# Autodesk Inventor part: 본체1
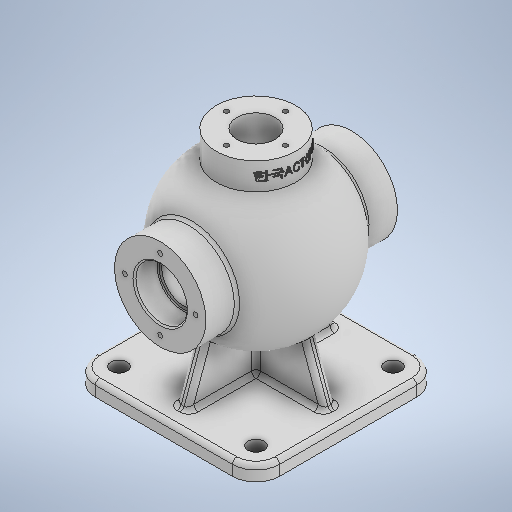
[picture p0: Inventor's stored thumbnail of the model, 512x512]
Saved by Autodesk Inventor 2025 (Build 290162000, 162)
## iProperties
Created: 2024-07
Part Number: 본체1
Material: 일반
Document SubType Name: Modeling
Designer: samsung
Density: 1 g/cm^3
Appearance: 기본값
Author: samsung
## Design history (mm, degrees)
sketch "스케치1"
  geometry: L1 (-46.5, -62.5)-(46.5, -62.5); L2 (62.5, -46.5)-(62.5, 46.5); L3 (46.5, 62.5)-(-46.5, 62.5); L4 (-62.5, 46.5)-(-62.5, -46.5); L5 (-62.5, -62.5)-(62.5, 62.5); L6 (62.5, -62.5)-(-62.5, 62.5); A1 r 16 centre (46.5, 46.5) between (62.5, 46.5) and (46.5, 62.5); A2 r 16 centre (-46.5, 46.5) between (-46.5, 62.5) and (-62.5, 46.5); A3 r 16 centre (-46.5, -46.5) between (-62.5, -46.5) and (-46.5, -62.5); A4 r 16 centre (46.5, -46.5) between (46.5, -62.5) and (62.5, -46.5); 1 further point
  constraints: 12 end point, 8 point on circle, 8 point on line, 8 tangent, 4 centre point, 3 equal radius, 2 midpoint, 2 parallel, 1 horizontal, 1 perpendicular
  dimensions: "d0" = 125 distance of L6.end L5.end; "d1" = 125 distance of L5.end L6.start; "d2" = 16 radius of A1
extrude "돌출1" new body sketch "스케치1" distance "d3" = 10; taper "d4" = 0 deg
sketch "스케치2"
  geometry: L1 (-46.5, 0)-(46.5, 0) reference; L2 (0, 139)-(0, 31); L3 (0, 139)-(0, 150.461); A1 r 54 centre (0, 85) between (0, 31) and (0, 139); A2 r 54 centre (0, 85) between (0, 139) and (0, 31); 3 further points
  constraints: 4 end point, 4 point on circle, 2 centre point, 2 midpoint, 2 vertical, 1 vertical alignment
  dimensions: "d5" = 108 diameter of A1; "d6" = 85 distance of point (0, 0) A1.centre; "d7" = 108 distance of L2.start L2.end
revolve "회전1" sketch "스케치2" stored, may be unused: angle "d8" = 90 deg
sketch "스케치3"
  geometry: C1 r 31 at (0, 85); 1 further point
  constraints: 1 centre point, 1 vertical alignment
  dimensions: "d9" = 62 diameter of C1; "d10" = 85 distance of point (0, 0) C1.centre
extrude "돌출2" join sketch "스케치3" stored distance "d11" = 130; taper "d12" = 0 deg
node "작업 평면1"
sketch "스케치4"
  geometry: C1 r 27 at (0, 0); 1 further point
  constraints: 1 centre point, 1 coincident
  dimensions: "d14" = 54 diameter of C1
extrude "돌출3" join sketch "스케치4" distance "d15" = 65; taper "d16" = 0 deg
sketch "스케치6"
  geometry: L1 (4, -50.5)-(-4, -50.5); L2 (-4, -50.5)-(-4, 50.5); L3 (-4, 50.5)-(4, 50.5); L4 (4, 50.5)-(4, -50.5); L5 (4, -50.5)-(-4, 50.5); L6 (-4, -50.5)-(4, 50.5); L7 (50.5, -4)-(-50.5, -4); L8 (-50.5, -4)-(-50.5, 4); L9 (-50.5, 4)-(50.5, 4); L10 (50.5, 4)-(50.5, -4); L11 (50.5, -4)-(-50.5, 4); L12 (-50.5, -4)-(50.5, 4); 6 further points
  constraints: 24 end point, 4 midpoint, 4 parallel, 2 horizontal, 2 perpendicular, 1 coincident
  dimensions: "d19" = 8 distance of L2.end L3.end; "d20" = 101 distance of L1.end L2.end; "d21" = 101 distance of L8.end L9.end; "d22" = 8 distance of L7.end L8.end
extrude "돌출4" join sketch "스케치6" distance "d23" = 75; taper "d24" = 0 deg
feature "면 기울기1" dims angle "d25" = 20 deg
feature "면 기울기2" dims angle "d26" = 20 deg
feature "면 기울기3" dims angle "d27" = 20 deg
feature "면 기울기4" dims angle "d28" = 20 deg
fillet "모깎기1" dims "d29" = 3
fillet "모깎기2" dims "d30" = 3
fillet "모깎기3" dims "d31" = 3
fillet "모깎기4" dims "d32" = 3
sketch "스케치7"
  geometry: L1 (46.5, 62.5)-(-46.5, 62.5) reference; L2 (62.5, -46.5)-(62.5, 46.5) reference; C1 r 5.5 at (46.5, 46.5); 1 further point
  constraints: 1 centre point
  dimensions: "d33" = 11 diameter of C1; "d34" = 16 distance from line of C1.centre L1; "d35" = 16 distance from line of L2 C1.centre
extrude "돌출5" cut sketch "스케치7" stored distance "d36" = 75; taper "d37" = 0 deg
sketch "스케치8"
  geometry: C1 r 31 at (0, 0) reference; C2 r 17.5 at (0, 0); 1 further point
  constraints: 1 centre point, 1 coincident
  dimensions: "d38" = 35 diameter of C2
extrude "돌출6" cut sketch "스케치8" distance "d39" = 16; taper "d40" = 0 deg
sketch "스케치9"
  geometry: C1 r 17.5 at (0, 0) reference; C2 r 15 at (0, 0); 1 further point
  constraints: 1 centre point, 1 coincident
  dimensions: "d45" = 30 diameter of C2
sketch "스케치10"
  geometry: L1 (0, 129)-(0, 41); L2 (0, 129)-(0, 137.625); A1 r 44 centre (0, 85) between (0, 41) and (0, 129); A2 r 44 centre (0, 85) between (0, 129) and (0, 41); 1 further point
  constraints: 4 end point, 4 point on circle, 2 centre point, 2 vertical, 1 vertical alignment
  dimensions: "d41" = 88 diameter of A1; "d42" = 85 distance of point (0, 0) A1.centre; "d43" = 88 distance of L1.start L1.end
revolve "회전2" sketch "스케치10" stored, may be unused: angle "d44" = 90 deg
extrude "돌출7" cut sketch "스케치9" stored distance "d46" = 10; taper "d47" = 0 deg
sketch "스케치11" dims "d48" = 48
  geometry: L1 (0, 0)-(0, 24); C1 r 17.5 at (0, 0) reference; 1 further point
  constraints: 2 end point, 1 coincident, 1 vertical, 1 vertical alignment, 2 other
hole "구멍1" sketch "스케치11" at (0, 24) diameter "d49" = 3.242; stored, may be unused: countersink angle "d53" = 82 deg, drill point angle "d55" = 120 deg; dims "d50" = 12, "d51" = 3.023, "d52" = 2, "d54" = 15
sketch "스케치12"
  geometry: C1 r 13 at (0, 0); 1 further point
  constraints: 1 centre point, 1 coincident
  dimensions: "d59" = 26 diameter of C1
extrude "돌출8" cut sketch "스케치12" stored distance "d60" = 10; taper "d61" = 0 deg
sketch "스케치13" dims "d62" = 40
  geometry: L1 (0, 0)-(0, 20); 1 further point
  constraints: 2 end point, 1 coincident, 1 vertical, 1 vertical alignment, 2 other
hole "구멍2" sketch "스케치13" at (0, 20) diameter "d63" = 3.242; stored, may be unused: countersink angle "d67" = 90 deg, drill point angle "d69" = 120 deg; dims "d64" = 9, "d65" = 4, "d66" = 2, "d68" = 11
chamfer "모따기1" distance "d73" = 1; stored, may be unused: second distance "d74" = 2, angle "d75" = 45 deg
fillet "모깎기5" dims "d76" = 0.6
fillet "모깎기6" dims "d77" = 3
node "작업 평면2"
sketch "스케치14"
  geometry: L1 (150, -27)-(150, 27) reference; 3 further points
  constraints: 1 horizontal alignment, 1 midpoint, 1 other
  dimensions: "d79" = 9 distance of point (150, 0) point (141, 0)
feature "엠보싱1" sketch "스케치14" dims "d5" = 108, "d6" = 85, "d7" = 108, "d80" = 0.5, "d81" = 0
node "솔리드1"
mirror "미러1"
mirror "미러2"
mirror "미러3"
pattern_circular "원형 패턴1" dims angle "d57" = 360 deg
mirror "미러4"
pattern_circular "원형 패턴2" dims angle "d71" = 360 deg
feature "A9D066F2-1C7D-4E18-AEED-F7BC21143FA4" dims "d49" = 3.242, "d50" = 12, "d51" = 3.023, "d52" = 2, "d53" = 82 deg, "d54" = 15, "d55" = 120 deg
other parameters: "d13" = 85, "d78" = 27
